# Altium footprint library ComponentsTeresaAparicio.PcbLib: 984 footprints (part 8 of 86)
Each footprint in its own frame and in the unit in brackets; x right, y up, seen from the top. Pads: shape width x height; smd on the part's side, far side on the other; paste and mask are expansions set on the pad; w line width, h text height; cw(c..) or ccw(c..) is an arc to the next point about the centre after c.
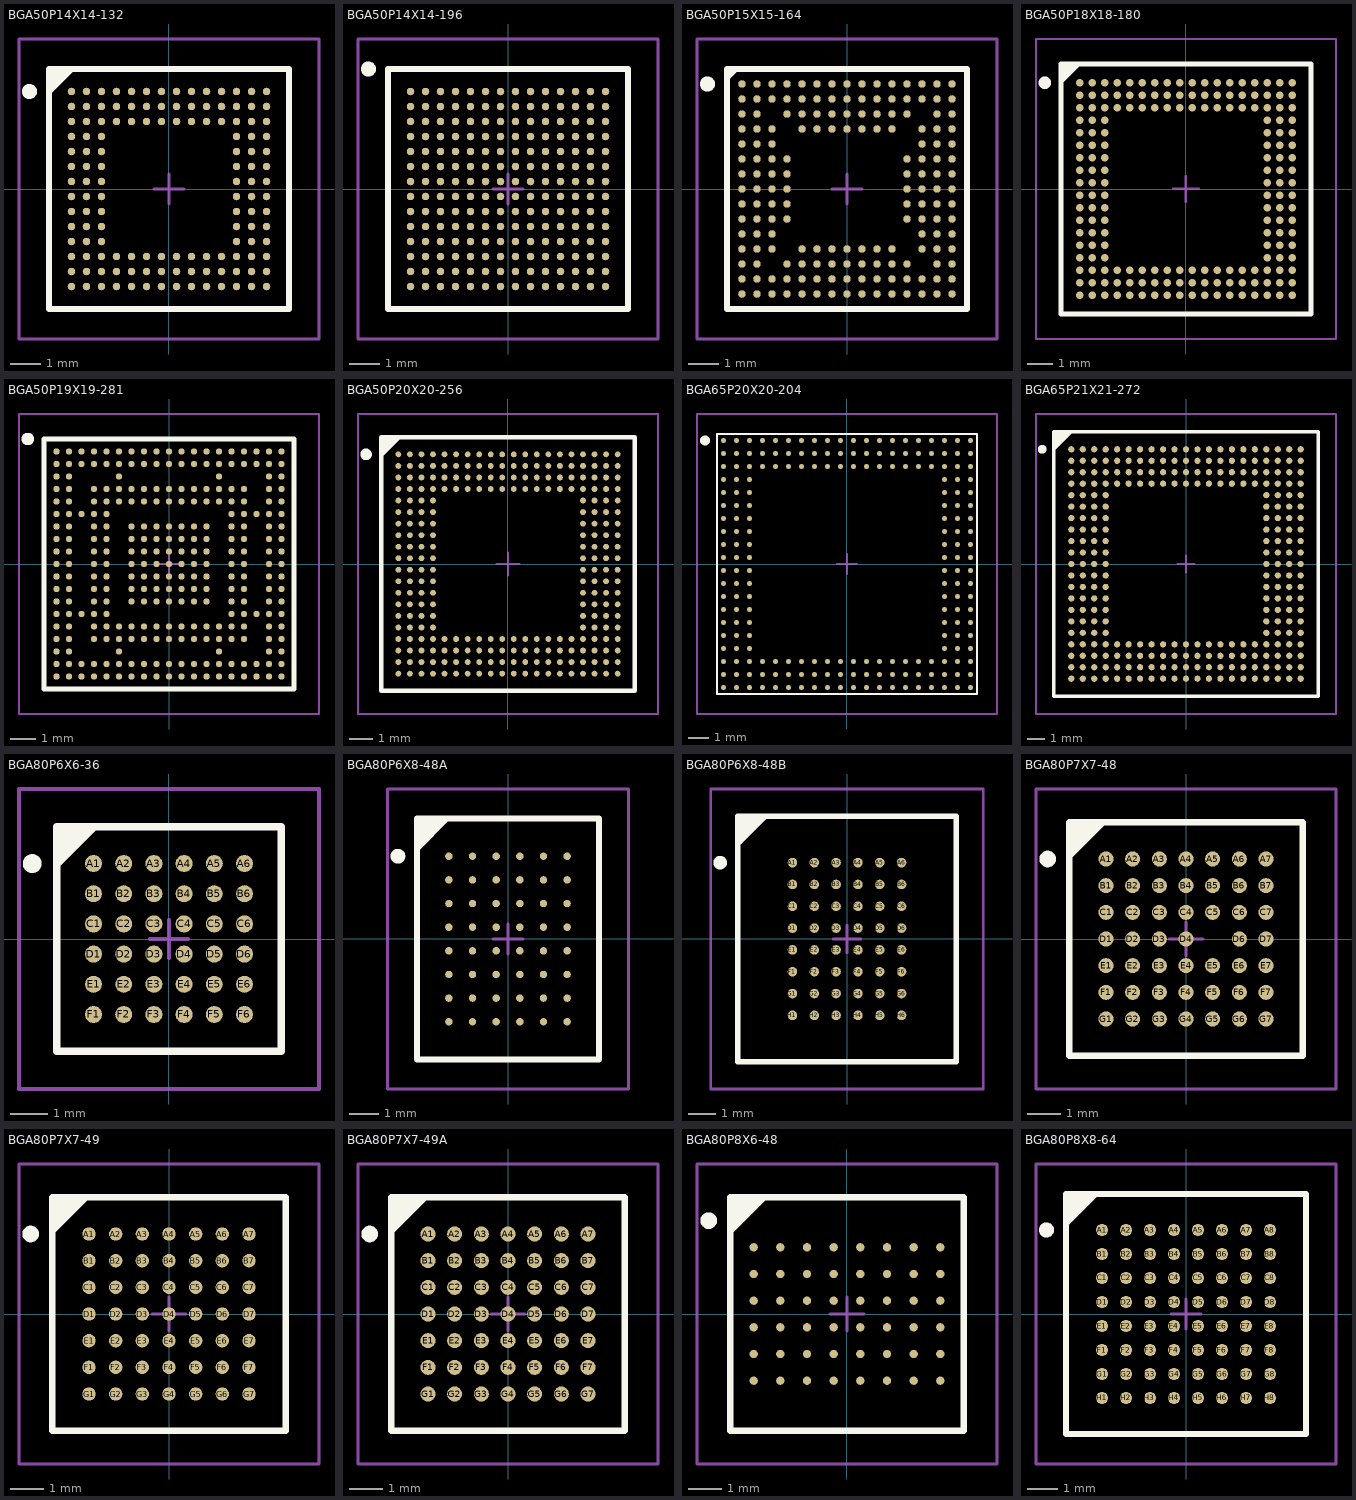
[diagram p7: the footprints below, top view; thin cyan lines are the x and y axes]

## BGA50P14X14-132 [mm] "BGA, 132-Leads, Body 8x8mm, Pitch 0.5mm"
height 1.35
pads (132):
  round 0.25 smd: A1(-3.25,3.25) A2(-2.75,3.25) A3(-2.25,3.25) A4(-1.75,3.25) A5(-1.25,3.25) A6(-0.75,3.25) A7(-0.25,3.25) A8(0.25,3.25) A9(0.75,3.25) A10(1.25,3.25) A11(1.75,3.25) A12(2.25,3.25) A13(2.75,3.25) A14(3.25,3.25) B1(-3.25,2.75) B2(-2.75,2.75) B3(-2.25,2.75) B4(-1.75,2.75) B5(-1.25,2.75) B6(-0.75,2.75) B7(-0.25,2.75) B8(0.25,2.75) B9(0.75,2.75) B10(1.25,2.75) B11(1.75,2.75) B12(2.25,2.75) B13(2.75,2.75) B14(3.25,2.75) C1(-3.25,2.25) C2(-2.75,2.25) C3(-2.25,2.25) C4(-1.75,2.25) C5(-1.25,2.25) C6(-0.75,2.25) C7(-0.25,2.25) C8(0.25,2.25) C9(0.75,2.25) C10(1.25,2.25) C11(1.75,2.25) C12(2.25,2.25) C13(2.75,2.25) C14(3.25,2.25) D1(-3.25,1.75) D2(-2.75,1.75) D3(-2.25,1.75) D12(2.25,1.75) D13(2.75,1.75) D14(3.25,1.75) E1(-3.25,1.25) E2(-2.75,1.25) E3(-2.25,1.25) E12(2.25,1.25) E13(2.75,1.25) E14(3.25,1.25) F1(-3.25,0.75) F2(-2.75,0.75) F3(-2.25,0.75) F12(2.25,0.75) F13(2.75,0.75) F14(3.25,0.75) G1(-3.25,0.25) G2(-2.75,0.25) G3(-2.25,0.25) G12(2.25,0.25) G13(2.75,0.25) G14(3.25,0.25) H1(-3.25,-0.25) H2(-2.75,-0.25) H3(-2.25,-0.25) H12(2.25,-0.25) H13(2.75,-0.25) H14(3.25,-0.25) J1(-3.25,-0.75) J2(-2.75,-0.75) J3(-2.25,-0.75) J12(2.25,-0.75) J13(2.75,-0.75) J14(3.25,-0.75) K1(-3.25,-1.25) K2(-2.75,-1.25) K3(-2.25,-1.25) K12(2.25,-1.25) K13(2.75,-1.25) K14(3.25,-1.25) L1(-3.25,-1.75) L2(-2.75,-1.75) L3(-2.25,-1.75) L12(2.25,-1.75) L13(2.75,-1.75) L14(3.25,-1.75) M1(-3.25,-2.25) M2(-2.75,-2.25) M3(-2.25,-2.25) M4(-1.75,-2.25) M5(-1.25,-2.25) M6(-0.75,-2.25) M7(-0.25,-2.25) M8(0.25,-2.25) M9(0.75,-2.25) M10(1.25,-2.25) M11(1.75,-2.25) M12(2.25,-2.25) M13(2.75,-2.25) M14(3.25,-2.25) N1(-3.25,-2.75) N2(-2.75,-2.75) N3(-2.25,-2.75) N4(-1.75,-2.75) N5(-1.25,-2.75) N6(-0.75,-2.75) N7(-0.25,-2.75) N8(0.25,-2.75) N9(0.75,-2.75) N10(1.25,-2.75) N11(1.75,-2.75) N12(2.25,-2.75) N13(2.75,-2.75) N14(3.25,-2.75) P1(-3.25,-3.25) P2(-2.75,-3.25) P3(-2.25,-3.25) P4(-1.75,-3.25) P5(-1.25,-3.25) P6(-0.75,-3.25) P7(-0.25,-3.25) P8(0.25,-3.25) P9(0.75,-3.25) P10(1.25,-3.25) P11(1.75,-3.25) P12(2.25,-3.25) P13(2.75,-3.25) P14(3.25,-3.25)
Top Overlay:
  circle w0.25: c-4.65,3.25 r0.125
  region: -3.242,4 -4,3.242 -4,4
  lines w0.2: -4,3.242 -3.242,4 ; -4,-4 -4,4 4,4 4,-4 -4,-4
Mechanical 13:
  lines w0.1: -4,-4 -4,4 4,4 4,-4 -4,-4
Mechanical 15:
  lines w0.1: -0.5,0 0.5,0 ; 0,-0.5 0,0.5 ; -5,-5 -5,5 5,5 5,-5 -5,-5
3D body: height 1.35, standoff 0, extent -4,-4 4,4

## BGA50P14X14-196 [mm] "BGA, 196-Leads, Body 8x8mm, Pitch 0.5mm"
height 1.2
pads (196):
  round 0.25 smd: A1(-3.25,3.25) A2(-2.75,3.25) A3(-2.25,3.25) A4(-1.75,3.25) A5(-1.25,3.25) A6(-0.75,3.25) A7(-0.25,3.25) A8(0.25,3.25) A9(0.75,3.25) A10(1.25,3.25) A11(1.75,3.25) A12(2.25,3.25) A13(2.75,3.25) A14(3.25,3.25) B1(-3.25,2.75) B2(-2.75,2.75) B3(-2.25,2.75) B4(-1.75,2.75) B5(-1.25,2.75) B6(-0.75,2.75) B7(-0.25,2.75) B8(0.25,2.75) B9(0.75,2.75) B10(1.25,2.75) B11(1.75,2.75) B12(2.25,2.75) B13(2.75,2.75) B14(3.25,2.75) C1(-3.25,2.25) C2(-2.75,2.25) C3(-2.25,2.25) C4(-1.75,2.25) C5(-1.25,2.25) C6(-0.75,2.25) C7(-0.25,2.25) C8(0.25,2.25) C9(0.75,2.25) C10(1.25,2.25) C11(1.75,2.25) C12(2.25,2.25) C13(2.75,2.25) C14(3.25,2.25) D1(-3.25,1.75) D2(-2.75,1.75) D3(-2.25,1.75) D4(-1.75,1.75) D5(-1.25,1.75) D6(-0.75,1.75) D7(-0.25,1.75) D8(0.25,1.75) D9(0.75,1.75) D10(1.25,1.75) D11(1.75,1.75) D12(2.25,1.75) D13(2.75,1.75) D14(3.25,1.75) E1(-3.25,1.25) E2(-2.75,1.25) E3(-2.25,1.25) E4(-1.75,1.25) E5(-1.25,1.25) E6(-0.75,1.25) E7(-0.25,1.25) E8(0.25,1.25) E9(0.75,1.25) E10(1.25,1.25) E11(1.75,1.25) E12(2.25,1.25) E13(2.75,1.25) E14(3.25,1.25) F1(-3.25,0.75) F2(-2.75,0.75) F3(-2.25,0.75) F4(-1.75,0.75) F5(-1.25,0.75) F6(-0.75,0.75) F7(-0.25,0.75) F8(0.25,0.75) F9(0.75,0.75) F10(1.25,0.75) F11(1.75,0.75) F12(2.25,0.75) F13(2.75,0.75) F14(3.25,0.75) G1(-3.25,0.25) G2(-2.75,0.25) G3(-2.25,0.25) G4(-1.75,0.25) G5(-1.25,0.25) G6(-0.75,0.25) G7(-0.25,0.25) G8(0.25,0.25) G9(0.75,0.25) G10(1.25,0.25) G11(1.75,0.25) G12(2.25,0.25) G13(2.75,0.25) G14(3.25,0.25) H1(-3.25,-0.25) H2(-2.75,-0.25) H3(-2.25,-0.25) H4(-1.75,-0.25) H5(-1.25,-0.25) H6(-0.75,-0.25) H7(-0.25,-0.25) H8(0.25,-0.25) H9(0.75,-0.25) H10(1.25,-0.25) H11(1.75,-0.25) H12(2.25,-0.25) H13(2.75,-0.25) H14(3.25,-0.25) J1(-3.25,-0.75) J2(-2.75,-0.75) J3(-2.25,-0.75) J4(-1.75,-0.75) J5(-1.25,-0.75) J6(-0.75,-0.75) J7(-0.25,-0.75) J8(0.25,-0.75) J9(0.75,-0.75) J10(1.25,-0.75) J11(1.75,-0.75) J12(2.25,-0.75) J13(2.75,-0.75) J14(3.25,-0.75) K1(-3.25,-1.25) K2(-2.75,-1.25) K3(-2.25,-1.25) K4(-1.75,-1.25) K5(-1.25,-1.25) K6(-0.75,-1.25) K7(-0.25,-1.25) K8(0.25,-1.25) K9(0.75,-1.25) K10(1.25,-1.25) K11(1.75,-1.25) K12(2.25,-1.25) K13(2.75,-1.25) K14(3.25,-1.25) L1(-3.25,-1.75) L2(-2.75,-1.75) L3(-2.25,-1.75) L4(-1.75,-1.75) L5(-1.25,-1.75) L6(-0.75,-1.75) L7(-0.25,-1.75) L8(0.25,-1.75) L9(0.75,-1.75) L10(1.25,-1.75) L11(1.75,-1.75) L12(2.25,-1.75) L13(2.75,-1.75) L14(3.25,-1.75) M1(-3.25,-2.25) M2(-2.75,-2.25) M3(-2.25,-2.25) M4(-1.75,-2.25) M5(-1.25,-2.25) M6(-0.75,-2.25) M7(-0.25,-2.25) M8(0.25,-2.25) M9(0.75,-2.25) M10(1.25,-2.25) M11(1.75,-2.25) M12(2.25,-2.25) M13(2.75,-2.25) M14(3.25,-2.25) N1(-3.25,-2.75) N2(-2.75,-2.75) N3(-2.25,-2.75) N4(-1.75,-2.75) N5(-1.25,-2.75) N6(-0.75,-2.75) N7(-0.25,-2.75) N8(0.25,-2.75) N9(0.75,-2.75) N10(1.25,-2.75) N11(1.75,-2.75) N12(2.25,-2.75) N13(2.75,-2.75) N14(3.25,-2.75) P1(-3.25,-3.25) P2(-2.75,-3.25) P3(-2.25,-3.25) P4(-1.75,-3.25) P5(-1.25,-3.25) P6(-0.75,-3.25) P7(-0.25,-3.25) P8(0.25,-3.25) P9(0.75,-3.25) P10(1.25,-3.25) P11(1.75,-3.25) P12(2.25,-3.25) P13(2.75,-3.25) P14(3.25,-3.25)
Top Overlay:
  circle w0.25: c-4.65,4 r0.125
  lines w0.2: -4,-4 4,-4 4,4 -4,4 -4,-4
Mechanical 13:
  lines w0.1: -4,-4 4,-4 4,4 -4,4 -4,-4
Mechanical 15:
  lines w0.1: -0.5,0 0.5,0 ; 0,-0.5 0,0.5 ; -5,-5 5,-5 5,5 -5,5 -5,-5
3D body: height 1.2, standoff 0.15, extent -4,-4 4,4

## BGA50P15X15-164 [mm] "BGA, 164-Leads, Body 8x8mm, Pitch 0.50mm"
height 1.2
pads (164):
  round 0.25 smd: A1(-3.5,3.5) A2(-3,3.5) A3(-2.5,3.5) A4(-2,3.5) A5(-1.5,3.5) A6(-1,3.5) A7(-0.5,3.5) A8(0,3.5) A9(0.5,3.5) A10(1,3.5) A11(1.5,3.5) A12(2,3.5) A13(2.5,3.5) A14(3,3.5) A15(3.5,3.5) B1(-3.5,3) B2(-3,3) B3(-2.5,3) B4(-2,3) B5(-1.5,3) B6(-1,3) B7(-0.5,3) B8(0,3) B9(0.5,3) B10(1,3) B11(1.5,3) B12(2,3) B13(2.5,3) B14(3,3) B15(3.5,3) C1(-3.5,2.5) C2(-3,2.5) C4(-2,2.5) C5(-1.5,2.5) C6(-1,2.5) C7(-0.5,2.5) C8(0,2.5) C9(0.5,2.5) C10(1,2.5) C11(1.5,2.5) C12(2,2.5) C14(3,2.5) C15(3.5,2.5) D1(-3.5,2) D2(-3,2) D3(-2.5,2) D5(-1.5,2) D6(-1,2) D7(-0.5,2) D8(0,2) D9(0.5,2) D10(1,2) D11(1.5,2) D13(2.5,2) D14(3,2) D15(3.5,2) E1(-3.5,1.5) E2(-3,1.5) E3(-2.5,1.5) E13(2.5,1.5) E14(3,1.5) E15(3.5,1.5) F1(-3.5,1) F2(-3,1) F3(-2.5,1) F4(-2,1) F12(2,1) F13(2.5,1) F14(3,1) F15(3.5,1) G1(-3.5,0.5) G2(-3,0.5) G3(-2.5,0.5) G4(-2,0.5) G12(2,0.5) G13(2.5,0.5) G14(3,0.5) G15(3.5,0.5) H1(-3.5,0) H2(-3,0) H3(-2.5,0) H4(-2,0) H12(2,0) H13(2.5,0) H14(3,0) H15(3.5,0) J1(-3.5,-0.5) J2(-3,-0.5) J3(-2.5,-0.5) J4(-2,-0.5) J12(2,-0.5) J13(2.5,-0.5) J14(3,-0.5) J15(3.5,-0.5) K1(-3.5,-1) K2(-3,-1) K3(-2.5,-1) K4(-2,-1) K12(2,-1) K13(2.5,-1) K14(3,-1) K15(3.5,-1) L1(-3.5,-1.5) L2(-3,-1.5) L3(-2.5,-1.5) L13(2.5,-1.5) L14(3,-1.5) L15(3.5,-1.5) M1(-3.5,-2) M2(-3,-2) M3(-2.5,-2) M5(-1.5,-2) M6(-1,-2) M7(-0.5,-2) M8(0,-2) M9(0.5,-2) M10(1,-2) M11(1.5,-2) M13(2.5,-2) M14(3,-2) M15(3.5,-2) N1(-3.5,-2.5) N2(-3,-2.5) N4(-2,-2.5) N5(-1.5,-2.5) N6(-1,-2.5) N7(-0.5,-2.5) N8(0,-2.5) N9(0.5,-2.5) N10(1,-2.5) N11(1.5,-2.5) N12(2,-2.5) N14(3,-2.5) N15(3.5,-2.5) P1(-3.5,-3) P2(-3,-3) P3(-2.5,-3) P4(-2,-3) P5(-1.5,-3) P6(-1,-3) P7(-0.5,-3) P8(0,-3) P9(0.5,-3) P10(1,-3) P11(1.5,-3) P12(2,-3) P13(2.5,-3) P14(3,-3) P15(3.5,-3) R1(-3.5,-3.5) R2(-3,-3.5) R3(-2.5,-3.5) R4(-2,-3.5) R5(-1.5,-3.5) R6(-1,-3.5) R7(-0.5,-3.5) R8(0,-3.5) R9(0.5,-3.5) R10(1,-3.5) R11(1.5,-3.5) R12(2,-3.5) R13(2.5,-3.5) R14(3,-3.5) R15(3.5,-3.5)
Top Overlay:
  circle w0.25: c-4.65,3.5 r0.125
  region: -3.707,4 -4,3.707 -4,4
  lines w0.2: -4,3.707 -3.707,4 ; -4,-4 -4,4 4,4 4,-4 -4,-4
Mechanical 13:
  lines w0.1: -4,-4 -4,4 4,4 4,-4 -4,-4
Mechanical 15:
  lines w0.1: -0.5,0 0.5,0 ; 0,-0.5 0,0.5 ; -5,-5 -5,5 5,5 5,-5 -5,-5
3D body: height 1.2, standoff 0.15, extent -4,-4 4,4

## BGA50P18X18-180 [mm] "BGA, 180-Leads, Body 10x10mm, Pitch 0.5mm"
height 1.11
pads (180):
  round 0.3 smd: A1(-4.25,4.25) A2(-3.75,4.25) A3(-3.25,4.25) A4(-2.75,4.25) A5(-2.25,4.25) A6(-1.75,4.25) A7(-1.25,4.25) A8(-0.75,4.25) A9(-0.25,4.25) A10(0.25,4.25) A11(0.75,4.25) A12(1.25,4.25) A13(1.75,4.25) A14(2.25,4.25) A15(2.75,4.25) A16(3.25,4.25) A17(3.75,4.25) A18(4.25,4.25) B1(-4.25,3.75) B2(-3.75,3.75) B3(-3.25,3.75) B4(-2.75,3.75) B5(-2.25,3.75) B6(-1.75,3.75) B7(-1.25,3.75) B8(-0.75,3.75) B9(-0.25,3.75) B10(0.25,3.75) B11(0.75,3.75) B12(1.25,3.75) B13(1.75,3.75) B14(2.25,3.75) B15(2.75,3.75) B16(3.25,3.75) B17(3.75,3.75) B18(4.25,3.75) C1(-4.25,3.25) C2(-3.75,3.25) C3(-3.25,3.25) C4(-2.75,3.25) C5(-2.25,3.25) C6(-1.75,3.25) C7(-1.25,3.25) C8(-0.75,3.25) C9(-0.25,3.25) C10(0.25,3.25) C11(0.75,3.25) C12(1.25,3.25) C13(1.75,3.25) C14(2.25,3.25) C15(2.75,3.25) C16(3.25,3.25) C17(3.75,3.25) C18(4.25,3.25) D1(-4.25,2.75) D2(-3.75,2.75) D3(-3.25,2.75) D16(3.25,2.75) D17(3.75,2.75) D18(4.25,2.75) E1(-4.25,2.25) E2(-3.75,2.25) E3(-3.25,2.25) E16(3.25,2.25) E17(3.75,2.25) E18(4.25,2.25) F1(-4.25,1.75) F2(-3.75,1.75) F3(-3.25,1.75) F16(3.25,1.75) F17(3.75,1.75) F18(4.25,1.75) G1(-4.25,1.25) G2(-3.75,1.25) G3(-3.25,1.25) G16(3.25,1.25) G17(3.75,1.25) G18(4.25,1.25) H1(-4.25,0.75) H2(-3.75,0.75) H3(-3.25,0.75) H16(3.25,0.75) H17(3.75,0.75) H18(4.25,0.75) J1(-4.25,0.25) J2(-3.75,0.25) J3(-3.25,0.25) J16(3.25,0.25) J17(3.75,0.25) J18(4.25,0.25) K1(-4.25,-0.25) K2(-3.75,-0.25) K3(-3.25,-0.25) K16(3.25,-0.25) K17(3.75,-0.25) K18(4.25,-0.25) L1(-4.25,-0.75) L2(-3.75,-0.75) L3(-3.25,-0.75) L16(3.25,-0.75) L17(3.75,-0.75) L18(4.25,-0.75) M1(-4.25,-1.25) M2(-3.75,-1.25) M3(-3.25,-1.25) M16(3.25,-1.25) M17(3.75,-1.25) M18(4.25,-1.25) N1(-4.25,-1.75) N2(-3.75,-1.75) N3(-3.25,-1.75) N16(3.25,-1.75) N17(3.75,-1.75) N18(4.25,-1.75) P1(-4.25,-2.25) P2(-3.75,-2.25) P3(-3.25,-2.25) P16(3.25,-2.25) P17(3.75,-2.25) P18(4.25,-2.25) R1(-4.25,-2.75) R2(-3.75,-2.75) R3(-3.25,-2.75) R16(3.25,-2.75) R17(3.75,-2.75) R18(4.25,-2.75) T1(-4.25,-3.25) T2(-3.75,-3.25) T3(-3.25,-3.25) T4(-2.75,-3.25) T5(-2.25,-3.25) T6(-1.75,-3.25) T7(-1.25,-3.25) T8(-0.75,-3.25) T9(-0.25,-3.25) T10(0.25,-3.25) T11(0.75,-3.25) T12(1.25,-3.25) T13(1.75,-3.25) T14(2.25,-3.25) T15(2.75,-3.25) T16(3.25,-3.25) T17(3.75,-3.25) T18(4.25,-3.25) U1(-4.25,-3.75) U2(-3.75,-3.75) U3(-3.25,-3.75) U4(-2.75,-3.75) U5(-2.25,-3.75) U6(-1.75,-3.75) U7(-1.25,-3.75) U8(-0.75,-3.75) U9(-0.25,-3.75) U10(0.25,-3.75) U11(0.75,-3.75) U12(1.25,-3.75) U13(1.75,-3.75) U14(2.25,-3.75) U15(2.75,-3.75) U16(3.25,-3.75) U17(3.75,-3.75) U18(4.25,-3.75) V1(-4.25,-4.25) V2(-3.75,-4.25) V3(-3.25,-4.25) V4(-2.75,-4.25) V5(-2.25,-4.25) V6(-1.75,-4.25) V7(-1.25,-4.25) V8(-0.75,-4.25) V9(-0.25,-4.25) V10(0.25,-4.25) V11(0.75,-4.25) V12(1.25,-4.25) V13(1.75,-4.25) V14(2.25,-4.25) V15(2.75,-4.25) V16(3.25,-4.25) V17(3.75,-4.25) V18(4.25,-4.25)
Top Overlay:
  circle w0.25: c-5.65,4.25 r0.125
  region: -4.306,5 -5,4.306 -5,5
  lines w0.2: -5,4.306 -4.306,5 ; -5,-5 -5,5 5,5 5,-5 -5,-5
Mechanical 13:
  lines w0.1: -5,-5 -5,5 5,5 5,-5 -5,-5
Mechanical 15:
  lines w0.1: -0.5,0 0.5,0 ; 0,-0.5 0,0.5 ; -6,-6 -6,6 6,6 6,-6 -6,-6
3D body: height 1.11, standoff 0.19, extent -5,-5 5,5

## BGA50P19X19-281 [mm] "BGA, 281-Leads, Body 10x10mm, Pitch 0.5mm"
height 1.05
pads (281):
  round 0.25 smd: A1(-4.5,4.5) A2(-4,4.5) A3(-3.5,4.5) A4(-3,4.5) A5(-2.5,4.5) A6(-2,4.5) A7(-1.5,4.5) A8(-1,4.5) A9(-0.5,4.5) A10(0,4.5) A11(0.5,4.5) A12(1,4.5) A13(1.5,4.5) A14(2,4.5) A15(2.5,4.5) A16(3,4.5) A17(3.5,4.5) A18(4,4.5) A19(4.5,4.5) B1(-4.5,4) B2(-4,4) B3(-3.5,4) B4(-3,4) B5(-2.5,4) B6(-2,4) B7(-1.5,4) B8(-1,4) B9(-0.5,4) B10(0,4) B11(0.5,4) B12(1,4) B13(1.5,4) B14(2,4) B15(2.5,4) B16(3,4) B17(3.5,4) B18(4,4) B19(4.5,4) C1(-4.5,3.5) C2(-4,3.5) C6(-2,3.5) C14(2,3.5) C18(4,3.5) C19(4.5,3.5) D1(-4.5,3) D2(-4,3) D4(-3,3) D5(-2.5,3) D6(-2,3) D7(-1.5,3) D8(-1,3) D9(-0.5,3) D10(0,3) D11(0.5,3) D12(1,3) D13(1.5,3) D14(2,3) D15(2.5,3) D16(3,3) D18(4,3) D19(4.5,3) E1(-4.5,2.5) E2(-4,2.5) E4(-3,2.5) E5(-2.5,2.5) E6(-2,2.5) E7(-1.5,2.5) E8(-1,2.5) E9(-0.5,2.5) E10(0,2.5) E11(0.5,2.5) E12(1,2.5) E13(1.5,2.5) E14(2,2.5) E15(2.5,2.5) E16(3,2.5) E18(4,2.5) E19(4.5,2.5) F1(-4.5,2) F2(-4,2) F3(-3.5,2) F4(-3,2) F5(-2.5,2) F15(2.5,2) F16(3,2) F17(3.5,2) F18(4,2) F19(4.5,2) G1(-4.5,1.5) G2(-4,1.5) G4(-3,1.5) G5(-2.5,1.5) G7(-1.5,1.5) G8(-1,1.5) G9(-0.5,1.5) G10(0,1.5) G11(0.5,1.5) G12(1,1.5) G13(1.5,1.5) G15(2.5,1.5) G16(3,1.5) G18(4,1.5) G19(4.5,1.5) H1(-4.5,1) H2(-4,1) H4(-3,1) H5(-2.5,1) H7(-1.5,1) H8(-1,1) H9(-0.5,1) H10(0,1) H11(0.5,1) H12(1,1) H13(1.5,1) H15(2.5,1) H16(3,1) H18(4,1) H19(4.5,1) J1(-4.5,0.5) J2(-4,0.5) J4(-3,0.5) J5(-2.5,0.5) J7(-1.5,0.5) J8(-1,0.5) J9(-0.5,0.5) J10(0,0.5) J11(0.5,0.5) J12(1,0.5) J13(1.5,0.5) J15(2.5,0.5) J16(3,0.5) J18(4,0.5) J19(4.5,0.5) K1(-4.5,0) K2(-4,0) K4(-3,0) K5(-2.5,0) K7(-1.5,0) K8(-1,0) K9(-0.5,0) K10(0,0) K11(0.5,0) K12(1,0) K13(1.5,0) K15(2.5,0) K16(3,0) K18(4,0) K19(4.5,0) L1(-4.5,-0.5) L2(-4,-0.5) L4(-3,-0.5) L5(-2.5,-0.5) L7(-1.5,-0.5) L8(-1,-0.5) L9(-0.5,-0.5) L10(0,-0.5) L11(0.5,-0.5) L12(1,-0.5) L13(1.5,-0.5) L15(2.5,-0.5) L16(3,-0.5) L18(4,-0.5) L19(4.5,-0.5) M1(-4.5,-1) M2(-4,-1) M4(-3,-1) M5(-2.5,-1) M7(-1.5,-1) M8(-1,-1) M9(-0.5,-1) M10(0,-1) M11(0.5,-1) M12(1,-1) M13(1.5,-1) M15(2.5,-1) M16(3,-1) M18(4,-1) M19(4.5,-1) N1(-4.5,-1.5) N2(-4,-1.5) N4(-3,-1.5) N5(-2.5,-1.5) N7(-1.5,-1.5) N8(-1,-1.5) N9(-0.5,-1.5) N10(0,-1.5) N11(0.5,-1.5) N12(1,-1.5) N13(1.5,-1.5) N15(2.5,-1.5) N16(3,-1.5) N18(4,-1.5) N19(4.5,-1.5) P1(-4.5,-2) P2(-4,-2) P3(-3.5,-2) P4(-3,-2) P5(-2.5,-2) P15(2.5,-2) P16(3,-2) P17(3.5,-2) P18(4,-2) P19(4.5,-2) R1(-4.5,-2.5) R2(-4,-2.5) R4(-3,-2.5) R5(-2.5,-2.5) R6(-2,-2.5) R7(-1.5,-2.5) R8(-1,-2.5) R9(-0.5,-2.5) R10(0,-2.5) R11(0.5,-2.5) R12(1,-2.5) R13(1.5,-2.5) R14(2,-2.5) R15(2.5,-2.5) R16(3,-2.5) R18(4,-2.5) R19(4.5,-2.5) T1(-4.5,-3) T2(-4,-3) T4(-3,-3) T5(-2.5,-3) T6(-2,-3) T7(-1.5,-3) T8(-1,-3) T9(-0.5,-3) T10(0,-3) T11(0.5,-3) T12(1,-3) T13(1.5,-3) T14(2,-3) T15(2.5,-3) T16(3,-3) T18(4,-3) T19(4.5,-3) U1(-4.5,-3.5) U2(-4,-3.5) U6(-2,-3.5) U14(2,-3.5) U18(4,-3.5) U19(4.5,-3.5) V1(-4.5,-4) V2(-4,-4) V3(-3.5,-4) V4(-3,-4) V5(-2.5,-4) V6(-2,-4) V7(-1.5,-4) V8(-1,-4) V9(-0.5,-4) V10(0,-4) V11(0.5,-4) V12(1,-4) V13(1.5,-4) V14(2,-4) V15(2.5,-4) V16(3,-4) V17(3.5,-4) V18(4,-4) V19(4.5,-4) W1(-4.5,-4.5) W2(-4,-4.5) W3(-3.5,-4.5) W4(-3,-4.5) W5(-2.5,-4.5) W6(-2,-4.5) W7(-1.5,-4.5) W8(-1,-4.5) W9(-0.5,-4.5) W10(0,-4.5) W11(0.5,-4.5) W12(1,-4.5) W13(1.5,-4.5) W14(2,-4.5) W15(2.5,-4.5) W16(3,-4.5) W17(3.5,-4.5) W18(4,-4.5) W19(4.5,-4.5)
Top Overlay:
  circle w0.25: c-5.65,5 r0.125
  lines w0.2: -5,-5 5,-5 5,5 -5,5 -5,-5
Mechanical 13:
  lines w0.1: -5,-5 5,-5 5,5 -5,5 -5,-5
Mechanical 15:
  lines w0.1: -0.5,0 0.5,0 ; 0,-0.5 0,0.5 ; -6,-6 6,-6 6,6 -6,6 -6,-6
3D body: height 1.05, standoff 0.18, extent -5,-5 5,5

## BGA50P20X20-256 [mm] "BGA, 256-Leads, Body 11x11mm, Pitch 0.5mm"
height 1.2
pads (256):
  round 0.25 smd: A1(-4.75,4.75) A2(-4.25,4.75) A3(-3.75,4.75) A4(-3.25,4.75) A5(-2.75,4.75) A6(-2.25,4.75) A7(-1.75,4.75) A8(-1.25,4.75) A9(-0.75,4.75) A10(-0.25,4.75) A11(0.25,4.75) A12(0.75,4.75) A13(1.25,4.75) A14(1.75,4.75) A15(2.25,4.75) A16(2.75,4.75) A17(3.25,4.75) A18(3.75,4.75) A19(4.25,4.75) A20(4.75,4.75) B1(-4.75,4.25) B2(-4.25,4.25) B3(-3.75,4.25) B4(-3.25,4.25) B5(-2.75,4.25) B6(-2.25,4.25) B7(-1.75,4.25) B8(-1.25,4.25) B9(-0.75,4.25) B10(-0.25,4.25) B11(0.25,4.25) B12(0.75,4.25) B13(1.25,4.25) B14(1.75,4.25) B15(2.25,4.25) B16(2.75,4.25) B17(3.25,4.25) B18(3.75,4.25) B19(4.25,4.25) B20(4.75,4.25) C1(-4.75,3.75) C2(-4.25,3.75) C3(-3.75,3.75) C4(-3.25,3.75) C5(-2.75,3.75) C6(-2.25,3.75) C7(-1.75,3.75) C8(-1.25,3.75) C9(-0.75,3.75) C10(-0.25,3.75) C11(0.25,3.75) C12(0.75,3.75) C13(1.25,3.75) C14(1.75,3.75) C15(2.25,3.75) C16(2.75,3.75) C17(3.25,3.75) C18(3.75,3.75) C19(4.25,3.75) C20(4.75,3.75) D1(-4.75,3.25) D2(-4.25,3.25) D3(-3.75,3.25) D4(-3.25,3.25) D5(-2.75,3.25) D6(-2.25,3.25) D7(-1.75,3.25) D8(-1.25,3.25) D9(-0.75,3.25) D10(-0.25,3.25) D11(0.25,3.25) D12(0.75,3.25) D13(1.25,3.25) D14(1.75,3.25) D15(2.25,3.25) D16(2.75,3.25) D17(3.25,3.25) D18(3.75,3.25) D19(4.25,3.25) D20(4.75,3.25) E1(-4.75,2.75) E2(-4.25,2.75) E3(-3.75,2.75) E4(-3.25,2.75) E17(3.25,2.75) E18(3.75,2.75) E19(4.25,2.75) E20(4.75,2.75) F1(-4.75,2.25) F2(-4.25,2.25) F3(-3.75,2.25) F4(-3.25,2.25) F17(3.25,2.25) F18(3.75,2.25) F19(4.25,2.25) F20(4.75,2.25) G1(-4.75,1.75) G2(-4.25,1.75) G3(-3.75,1.75) G4(-3.25,1.75) G17(3.25,1.75) G18(3.75,1.75) G19(4.25,1.75) G20(4.75,1.75) H1(-4.75,1.25) H2(-4.25,1.25) H3(-3.75,1.25) H4(-3.25,1.25) H17(3.25,1.25) H18(3.75,1.25) H19(4.25,1.25) H20(4.75,1.25) J1(-4.75,0.75) J2(-4.25,0.75) J3(-3.75,0.75) J4(-3.25,0.75) J17(3.25,0.75) J18(3.75,0.75) J19(4.25,0.75) J20(4.75,0.75) K1(-4.75,0.25) K2(-4.25,0.25) K3(-3.75,0.25) K4(-3.25,0.25) K17(3.25,0.25) K18(3.75,0.25) K19(4.25,0.25) K20(4.75,0.25) L1(-4.75,-0.25) L2(-4.25,-0.25) L3(-3.75,-0.25) L4(-3.25,-0.25) L17(3.25,-0.25) L18(3.75,-0.25) L19(4.25,-0.25) L20(4.75,-0.25) M1(-4.75,-0.75) M2(-4.25,-0.75) M3(-3.75,-0.75) M4(-3.25,-0.75) M17(3.25,-0.75) M18(3.75,-0.75) M19(4.25,-0.75) M20(4.75,-0.75) N1(-4.75,-1.25) N2(-4.25,-1.25) N3(-3.75,-1.25) N4(-3.25,-1.25) N17(3.25,-1.25) N18(3.75,-1.25) N19(4.25,-1.25) N20(4.75,-1.25) P1(-4.75,-1.75) P2(-4.25,-1.75) P3(-3.75,-1.75) P4(-3.25,-1.75) P17(3.25,-1.75) P18(3.75,-1.75) P19(4.25,-1.75) P20(4.75,-1.75) R1(-4.75,-2.25) R2(-4.25,-2.25) R3(-3.75,-2.25) R4(-3.25,-2.25) R17(3.25,-2.25) R18(3.75,-2.25) R19(4.25,-2.25) R20(4.75,-2.25) T1(-4.75,-2.75) T2(-4.25,-2.75) T3(-3.75,-2.75) T4(-3.25,-2.75) T17(3.25,-2.75) T18(3.75,-2.75) T19(4.25,-2.75) T20(4.75,-2.75) U1(-4.75,-3.25) U2(-4.25,-3.25) U3(-3.75,-3.25) U4(-3.25,-3.25) U5(-2.75,-3.25) U6(-2.25,-3.25) U7(-1.75,-3.25) U8(-1.25,-3.25) U9(-0.75,-3.25) U10(-0.25,-3.25) U11(0.25,-3.25) U12(0.75,-3.25) U13(1.25,-3.25) U14(1.75,-3.25) U15(2.25,-3.25) U16(2.75,-3.25) U17(3.25,-3.25) U18(3.75,-3.25) U19(4.25,-3.25) U20(4.75,-3.25) V1(-4.75,-3.75) V2(-4.25,-3.75) V3(-3.75,-3.75) V4(-3.25,-3.75) V5(-2.75,-3.75) V6(-2.25,-3.75) V7(-1.75,-3.75) V8(-1.25,-3.75) V9(-0.75,-3.75) V10(-0.25,-3.75) V11(0.25,-3.75) V12(0.75,-3.75) V13(1.25,-3.75) V14(1.75,-3.75) V15(2.25,-3.75) V16(2.75,-3.75) V17(3.25,-3.75) V18(3.75,-3.75) V19(4.25,-3.75) V20(4.75,-3.75) W1(-4.75,-4.25) W2(-4.25,-4.25) W3(-3.75,-4.25) W4(-3.25,-4.25) W5(-2.75,-4.25) W6(-2.25,-4.25) W7(-1.75,-4.25) W8(-1.25,-4.25) W9(-0.75,-4.25) W10(-0.25,-4.25) W11(0.25,-4.25) W12(0.75,-4.25) W13(1.25,-4.25) W14(1.75,-4.25) W15(2.25,-4.25) W16(2.75,-4.25) W17(3.25,-4.25) W18(3.75,-4.25) W19(4.25,-4.25) W20(4.75,-4.25) Y1(-4.75,-4.75) Y2(-4.25,-4.75) Y3(-3.75,-4.75) Y4(-3.25,-4.75) Y5(-2.75,-4.75) Y6(-2.25,-4.75) Y7(-1.75,-4.75) Y8(-1.25,-4.75) Y9(-0.75,-4.75) Y10(-0.25,-4.75) Y11(0.25,-4.75) Y12(0.75,-4.75) Y13(1.25,-4.75) Y14(1.75,-4.75) Y15(2.25,-4.75) Y16(2.75,-4.75) Y17(3.25,-4.75) Y18(3.75,-4.75) Y19(4.25,-4.75) Y20(4.75,-4.75)
Top Overlay:
  circle w0.25: c-6.15,4.75 r0.125
  region: -4.742,5.5 -5.5,4.742 -5.5,5.5
  lines w0.2: -5.5,4.742 -4.742,5.5 ; -5.5,-5.5 5.5,-5.5 5.5,5.5 -5.5,5.5 -5.5,-5.5
Mechanical 13:
  lines w0.1: -5.5,-5.5 5.5,-5.5 5.5,5.5 -5.5,5.5 -5.5,-5.5
Mechanical 15:
  lines w0.1: -0.5,0 0.5,0 ; 0,-0.5 0,0.5 ; -6.5,-6.5 6.5,-6.5 6.5,6.5 -6.5,6.5 -6.5,-6.5
3D body: height 0, standoff 0, extent -5.499,-5.499 5.499,5.499

## BGA65P20X20-204 [mm] "BGA, 204-Leads, Body 13x13mm, Pitch 0.65mm"
height 1.2
pads (204):
  round 0.25 smd: A1(-6.175,6.175) A2(-5.525,6.175) A3(-4.875,6.175) A4(-4.225,6.175) A5(-3.575,6.175) A6(-2.925,6.175) A7(-2.275,6.175) A8(-1.625,6.175) A9(-0.975,6.175) A10(-0.325,6.175) A11(0.325,6.175) A12(0.975,6.175) A13(1.625,6.175) A14(2.275,6.175) A15(2.925,6.175) A16(3.575,6.175) A17(4.225,6.175) A18(4.875,6.175) A19(5.525,6.175) A20(6.175,6.175) B1(-6.175,5.525) B2(-5.525,5.525) B3(-4.875,5.525) B4(-4.225,5.525) B5(-3.575,5.525) B6(-2.925,5.525) B7(-2.275,5.525) B8(-1.625,5.525) B9(-0.975,5.525) B10(-0.325,5.525) B11(0.325,5.525) B12(0.975,5.525) B13(1.625,5.525) B14(2.275,5.525) B15(2.925,5.525) B16(3.575,5.525) B17(4.225,5.525) B18(4.875,5.525) B19(5.525,5.525) B20(6.175,5.525) C1(-6.175,4.875) C2(-5.525,4.875) C3(-4.875,4.875) C4(-4.225,4.875) C5(-3.575,4.875) C6(-2.925,4.875) C7(-2.275,4.875) C8(-1.625,4.875) C9(-0.975,4.875) C10(-0.325,4.875) C11(0.325,4.875) C12(0.975,4.875) C13(1.625,4.875) C14(2.275,4.875) C15(2.925,4.875) C16(3.575,4.875) C17(4.225,4.875) C18(4.875,4.875) C19(5.525,4.875) C20(6.175,4.875) D1(-6.175,4.225) D2(-5.525,4.225) D3(-4.875,4.225) D18(4.875,4.225) D19(5.525,4.225) D20(6.175,4.225) E1(-6.175,3.575) E2(-5.525,3.575) E3(-4.875,3.575) E18(4.875,3.575) E19(5.525,3.575) E20(6.175,3.575) F1(-6.175,2.925) F2(-5.525,2.925) F3(-4.875,2.925) F18(4.875,2.925) F19(5.525,2.925) F20(6.175,2.925) G1(-6.175,2.275) G2(-5.525,2.275) G3(-4.875,2.275) G18(4.875,2.275) G19(5.525,2.275) G20(6.175,2.275) H1(-6.175,1.625) H2(-5.525,1.625) H3(-4.875,1.625) H18(4.875,1.625) H19(5.525,1.625) H20(6.175,1.625) J1(-6.175,0.975) J2(-5.525,0.975) J3(-4.875,0.975) J18(4.875,0.975) J19(5.525,0.975) J20(6.175,0.975) K1(-6.175,0.325) K2(-5.525,0.325) K3(-4.875,0.325) K18(4.875,0.325) K19(5.525,0.325) K20(6.175,0.325) L1(-6.175,-0.325) L2(-5.525,-0.325) L3(-4.875,-0.325) L18(4.875,-0.325) L19(5.525,-0.325) L20(6.175,-0.325) M1(-6.175,-0.975) M2(-5.525,-0.975) M3(-4.875,-0.975) M18(4.875,-0.975) M19(5.525,-0.975) M20(6.175,-0.975) N1(-6.175,-1.625) N2(-5.525,-1.625) N3(-4.875,-1.625) N18(4.875,-1.625) N19(5.525,-1.625) N20(6.175,-1.625) P1(-6.175,-2.275) P2(-5.525,-2.275) P3(-4.875,-2.275) P18(4.875,-2.275) P19(5.525,-2.275) P20(6.175,-2.275) R1(-6.175,-2.925) R2(-5.525,-2.925) R3(-4.875,-2.925) R18(4.875,-2.925) R19(5.525,-2.925) R20(6.175,-2.925) T1(-6.175,-3.575) T2(-5.525,-3.575) T3(-4.875,-3.575) T18(4.875,-3.575) T19(5.525,-3.575) T20(6.175,-3.575) U1(-6.175,-4.225) U2(-5.525,-4.225) U3(-4.875,-4.225) U18(4.875,-4.225) U19(5.525,-4.225) U20(6.175,-4.225) V1(-6.175,-4.875) V2(-5.525,-4.875) V3(-4.875,-4.875) V4(-4.225,-4.875) V5(-3.575,-4.875) V6(-2.925,-4.875) V7(-2.275,-4.875) V8(-1.625,-4.875) V9(-0.975,-4.875) V10(-0.325,-4.875) V11(0.325,-4.875) V12(0.975,-4.875) V13(1.625,-4.875) V14(2.275,-4.875) V15(2.925,-4.875) V16(3.575,-4.875) V17(4.225,-4.875) V18(4.875,-4.875) V19(5.525,-4.875) V20(6.175,-4.875) W1(-6.175,-5.525) W2(-5.525,-5.525) W3(-4.875,-5.525) W4(-4.225,-5.525) W5(-3.575,-5.525) W6(-2.925,-5.525) W7(-2.275,-5.525) W8(-1.625,-5.525) W9(-0.975,-5.525) W10(-0.325,-5.525) W11(0.325,-5.525) W12(0.975,-5.525) W13(1.625,-5.525) W14(2.275,-5.525) W15(2.925,-5.525) W16(3.575,-5.525) W17(4.225,-5.525) W18(4.875,-5.525) W19(5.525,-5.525) W20(6.175,-5.525) Y1(-6.175,-6.175) Y2(-5.525,-6.175) Y3(-4.875,-6.175) Y4(-4.225,-6.175) Y5(-3.575,-6.175) Y6(-2.925,-6.175) Y7(-2.275,-6.175) Y8(-1.625,-6.175) Y9(-0.975,-6.175) Y10(-0.325,-6.175) Y11(0.325,-6.175) Y12(0.975,-6.175) Y13(1.625,-6.175) Y14(2.275,-6.175) Y15(2.925,-6.175) Y16(3.575,-6.175) Y17(4.225,-6.175) Y18(4.875,-6.175) Y19(5.525,-6.175) Y20(6.175,-6.175)
Top Overlay:
  circle w0.25: c-7.1,6.175 r0.125
  lines w0.1: -6.5,-6.5 6.5,-6.5 6.5,6.5 -6.5,6.5 -6.5,-6.5
Mechanical 13:
  lines w0.1: -6.5,-6.5 6.5,-6.5 6.5,6.5 -6.5,6.5 -6.5,-6.5
Mechanical 15:
  lines w0.1: -0.5,0 0.5,0 ; 0,-0.5 0,0.5 ; -7.5,-7.5 7.5,-7.5 7.5,7.5 -7.5,7.5 -7.5,-7.5
3D body: height 1.2, standoff 0.2, extent -6.5,-6.5 6.5,6.5

## BGA65P21X21-272 [mm] "BGA, 209-Leads, Body 13x13mm, Pitch 0.65mm"
height 1.3
pads (272):
  round 0.35 smd: A1(-6.5,6.5) A2(-5.85,6.5) A3(-5.2,6.5) A4(-4.55,6.5) A5(-3.9,6.5) A6(-3.25,6.5) A7(-2.6,6.5) A8(-1.95,6.5) A9(-1.3,6.5) A10(-0.65,6.5) A11(0,6.5) A12(0.65,6.5) A13(1.3,6.5) A14(1.95,6.5) A15(2.6,6.5) A16(3.25,6.5) A17(3.9,6.5) A18(4.55,6.5) A19(5.2,6.5) A20(5.85,6.5) A21(6.5,6.5) AA1(-6.5,-6.5) AA2(-5.85,-6.5) AA3(-5.2,-6.5) AA4(-4.55,-6.5) AA5(-3.9,-6.5) AA6(-3.25,-6.5) AA7(-2.6,-6.5) AA8(-1.95,-6.5) AA9(-1.3,-6.5) AA10(-0.65,-6.5) AA11(0,-6.5) AA12(0.65,-6.5) AA13(1.3,-6.5) AA14(1.95,-6.5) AA15(2.6,-6.5) AA16(3.25,-6.5) AA17(3.9,-6.5) AA18(4.55,-6.5) AA19(5.2,-6.5) AA20(5.85,-6.5) AA21(6.5,-6.5) B1(-6.5,5.85) B2(-5.85,5.85) B3(-5.2,5.85) B4(-4.55,5.85) B5(-3.9,5.85) B6(-3.25,5.85) B7(-2.6,5.85) B8(-1.95,5.85) B9(-1.3,5.85) B10(-0.65,5.85) B11(0,5.85) B12(0.65,5.85) B13(1.3,5.85) B14(1.95,5.85) B15(2.6,5.85) B16(3.25,5.85) B17(3.9,5.85) B18(4.55,5.85) B19(5.2,5.85) B20(5.85,5.85) B21(6.5,5.85) C1(-6.5,5.2) C2(-5.85,5.2) C3(-5.2,5.2) C4(-4.55,5.2) C5(-3.9,5.2) C6(-3.25,5.2) C7(-2.6,5.2) C8(-1.95,5.2) C9(-1.3,5.2) C10(-0.65,5.2) C11(0,5.2) C12(0.65,5.2) C13(1.3,5.2) C14(1.95,5.2) C15(2.6,5.2) C16(3.25,5.2) C17(3.9,5.2) C18(4.55,5.2) C19(5.2,5.2) C20(5.85,5.2) C21(6.5,5.2) D1(-6.5,4.55) D2(-5.85,4.55) D3(-5.2,4.55) D4(-4.55,4.55) D5(-3.9,4.55) D6(-3.25,4.55) D7(-2.6,4.55) D8(-1.95,4.55) D9(-1.3,4.55) D10(-0.65,4.55) D11(0,4.55) D12(0.65,4.55) D13(1.3,4.55) D14(1.95,4.55) D15(2.6,4.55) D16(3.25,4.55) D17(3.9,4.55) D18(4.55,4.55) D19(5.2,4.55) D20(5.85,4.55) D21(6.5,4.55) E1(-6.5,3.9) E2(-5.85,3.9) E3(-5.2,3.9) E4(-4.55,3.9) E18(4.55,3.9) E19(5.2,3.9) E20(5.85,3.9) E21(6.5,3.9) F1(-6.5,3.25) F2(-5.85,3.25) F3(-5.2,3.25) F4(-4.55,3.25) F18(4.55,3.25) F19(5.2,3.25) F20(5.85,3.25) F21(6.5,3.25) G1(-6.5,2.6) G2(-5.85,2.6) G3(-5.2,2.6) G4(-4.55,2.6) G18(4.55,2.6) G19(5.2,2.6) G20(5.85,2.6) G21(6.5,2.6) H1(-6.5,1.95) H2(-5.85,1.95) H3(-5.2,1.95) H4(-4.55,1.95) H18(4.55,1.95) H19(5.2,1.95) H20(5.85,1.95) H21(6.5,1.95) J1(-6.5,1.3) J2(-5.85,1.3) J3(-5.2,1.3) J4(-4.55,1.3) J18(4.55,1.3) J19(5.2,1.3) J20(5.85,1.3) J21(6.5,1.3) K1(-6.5,0.65) K2(-5.85,0.65) K3(-5.2,0.65) K4(-4.55,0.65) K18(4.55,0.65) K19(5.2,0.65) K20(5.85,0.65) K21(6.5,0.65) L1(-6.5,0) L2(-5.85,0) L3(-5.2,0) L4(-4.55,0) L18(4.55,0) L19(5.2,0) L20(5.85,0) L21(6.5,0) M1(-6.5,-0.65) M2(-5.85,-0.65) M3(-5.2,-0.65) M4(-4.55,-0.65) M18(4.55,-0.65) M19(5.2,-0.65) M20(5.85,-0.65) M21(6.5,-0.65) N1(-6.5,-1.3) N2(-5.85,-1.3) N3(-5.2,-1.3) N4(-4.55,-1.3) N18(4.55,-1.3) N19(5.2,-1.3) N20(5.85,-1.3) N21(6.5,-1.3) P1(-6.5,-1.95) P2(-5.85,-1.95) P3(-5.2,-1.95) P4(-4.55,-1.95) P18(4.55,-1.95) P19(5.2,-1.95) P20(5.85,-1.95) P21(6.5,-1.95) R1(-6.5,-2.6) R2(-5.85,-2.6) R3(-5.2,-2.6) R4(-4.55,-2.6) R18(4.55,-2.6) R19(5.2,-2.6) R20(5.85,-2.6) R21(6.5,-2.6) T1(-6.5,-3.25) T2(-5.85,-3.25) T3(-5.2,-3.25) T4(-4.55,-3.25) T18(4.55,-3.25) T19(5.2,-3.25) T20(5.85,-3.25) T21(6.5,-3.25) U1(-6.5,-3.9) U2(-5.85,-3.9) U3(-5.2,-3.9) U4(-4.55,-3.9) U18(4.55,-3.9) U19(5.2,-3.9) U20(5.85,-3.9) U21(6.5,-3.9) V1(-6.5,-4.55) V2(-5.85,-4.55) V3(-5.2,-4.55) V4(-4.55,-4.55) V5(-3.9,-4.55) V6(-3.25,-4.55) V7(-2.6,-4.55) V8(-1.95,-4.55) V9(-1.3,-4.55) V10(-0.65,-4.55) V11(0,-4.55) V12(0.65,-4.55) V13(1.3,-4.55) V14(1.95,-4.55) V15(2.6,-4.55) V16(3.25,-4.55) V17(3.9,-4.55) V18(4.55,-4.55) V19(5.2,-4.55) V20(5.85,-4.55) V21(6.5,-4.55) W1(-6.5,-5.2) W2(-5.85,-5.2) W3(-5.2,-5.2) W4(-4.55,-5.2) W5(-3.9,-5.2) W6(-3.25,-5.2) W7(-2.6,-5.2) W8(-1.95,-5.2) W9(-1.3,-5.2) W10(-0.65,-5.2) W11(0,-5.2) W12(0.65,-5.2) W13(1.3,-5.2) W14(1.95,-5.2) W15(2.6,-5.2) W16(3.25,-5.2) W17(3.9,-5.2) W18(4.55,-5.2) W19(5.2,-5.2) W20(5.85,-5.2) W21(6.5,-5.2) Y1(-6.5,-5.85) Y2(-5.85,-5.85) Y3(-5.2,-5.85) Y4(-4.55,-5.85) Y5(-3.9,-5.85) Y6(-3.25,-5.85) Y7(-2.6,-5.85) Y8(-1.95,-5.85) Y9(-1.3,-5.85) Y10(-0.65,-5.85) Y11(0,-5.85) Y12(0.65,-5.85) Y13(1.3,-5.85) Y14(1.95,-5.85) Y15(2.6,-5.85) Y16(3.25,-5.85) Y17(3.9,-5.85) Y18(4.55,-5.85) Y19(5.2,-5.85) Y20(5.85,-5.85) Y21(6.5,-5.85)
Top Overlay:
  circle w0.25: c-8.15,6.5 r0.125
  region: -6.5,7.5 -7.5,6.5 -7.5,7.5
  lines w0.2: -7.5,6.5 -6.5,7.5 ; -7.5,-7.5 7.5,-7.5 7.5,7.5 -7.5,7.5 -7.5,-7.5
Mechanical 13:
  lines w0.1: -7.5,-7.5 7.5,-7.5 7.5,7.5 -7.5,7.5 -7.5,-7.5
Mechanical 15:
  lines w0.1: -0.5,0 0.5,0 ; 0,-0.5 0,0.5 ; -8.5,-8.5 8.5,-8.5 8.5,8.5 -8.5,8.5 -8.5,-8.5
3D body: height 1.3, standoff 0.4, extent -7.5,-7.5 7.5,7.5

## BGA80P6X6-36 [mm] "36-Ball Low Profile Ball Grid Array 0.8 mm Pitch"
height 1.7
pads (36):
  round 0.45 smd: A1(-2,2) A2(-1.2,2) A3(-0.4,2) A4(0.4,2) A5(1.2,2) A6(2,2) B1(-2,1.2) B2(-1.2,1.2) B3(-0.4,1.2) B4(0.4,1.2) B5(1.2,1.2) B6(2,1.2) C1(-2,0.4) C2(-1.2,0.4) C3(-0.4,0.4) C4(0.4,0.4) C5(1.2,0.4) C6(2,0.4) D1(-2,-0.4) D2(-1.2,-0.4) D3(-0.4,-0.4) D4(0.4,-0.4) D5(1.2,-0.4) D6(2,-0.4) E1(-2,-1.2) E2(-1.2,-1.2) E3(-0.4,-1.2) E4(0.4,-1.2) E5(1.2,-1.2) E6(2,-1.2) F1(-2,-2) F2(-1.2,-2) F3(-0.4,-2) F4(0.4,-2) F5(1.2,-2) F6(2,-2)
Top Overlay:
  circle w0.25: c-3.625,2 r0.125
  region: -1.975,2.975 -2.975,1.975 -2.975,2.975
  lines w0.2: -2.975,1.975 -1.975,2.975 ; -2.975,-2.975 -2.975,2.975 2.975,2.975 2.975,-2.975 -2.975,-2.975
Mechanical 13:
  lines w0.1: -2.975,-2.975 -2.975,2.975 2.975,2.975 2.975,-2.975 -2.975,-2.975
Mechanical 15:
  lines w0.1: -0.5,0 0.5,0 ; 0,-0.5 0,0.5 ; -3.975,-3.975 -3.975,3.975 3.975,3.975 3.975,-3.975 -3.975,-3.975
3D body: height 1.7, standoff 0, extent -2.975,-2.975 2.975,2.975

## BGA80P6X8-48A [mm] "48-Ball Fine Pitch Ball Grid Array Rectangular 0.8 mm Pitch"
height 1.2
pads (48):
  round 0.25 smd: A1(-2,2.8) A2(-1.2,2.8) A3(-0.4,2.8) A4(0.4,2.8) A5(1.2,2.8) A6(2,2.8) B1(-2,2) B2(-1.2,2) B3(-0.4,2) B4(0.4,2) B5(1.2,2) B6(2,2) C1(-2,1.2) C2(-1.2,1.2) C3(-0.4,1.2) C4(0.4,1.2) C5(1.2,1.2) C6(2,1.2) D1(-2,0.4) D2(-1.2,0.4) D3(-0.4,0.4) D4(0.4,0.4) D5(1.2,0.4) D6(2,0.4) E1(-2,-0.4) E2(-1.2,-0.4) E3(-0.4,-0.4) E4(0.4,-0.4) E5(1.2,-0.4) E6(2,-0.4) F1(-2,-1.2) F2(-1.2,-1.2) F3(-0.4,-1.2) F4(0.4,-1.2) F5(1.2,-1.2) F6(2,-1.2) G1(-2,-2) G2(-1.2,-2) G3(-0.4,-2) G4(0.4,-2) G5(1.2,-2) G6(2,-2) H1(-2,-2.8) H2(-1.2,-2.8) H3(-0.4,-2.8) H4(0.4,-2.8) H5(1.2,-2.8) H6(2,-2.8)
Top Overlay:
  circle w0.25: c-3.725,2.8 r0.125
  region: -2.075,4.075 -3.075,3.075 -3.075,4.075
  lines w0.2: -3.075,3.075 -2.075,4.075 ; -3.075,-4.075 -3.075,4.075 3.075,4.075 3.075,-4.075 -3.075,-4.075
Mechanical 13:
  lines w0.1: -3.075,-4.075 -3.075,4.075 3.075,4.075 3.075,-4.075 -3.075,-4.075
Mechanical 15:
  lines w0.1: -0.5,0 0.5,0 ; 0,-0.5 0,0.5 ; -4.075,-5.075 -4.075,5.075 4.075,5.075 4.075,-5.075 -4.075,-5.075
3D body: height 1.2, standoff 0, extent -3.075,-4.075 3.075,4.075

## BGA80P6X8-48B [mm] "BGA, 48-Leads, Body 9x8mm, Pitch 0.8mm"
height 1.2
pads (48):
  round 0.35 smd: A1(-2,2.8) A2(-1.2,2.8) A3(-0.4,2.8) A4(0.4,2.8) A5(1.2,2.8) A6(2,2.8) B1(-2,2) B2(-1.2,2) B3(-0.4,2) B4(0.4,2) B5(1.2,2) B6(2,2) C1(-2,1.2) C2(-1.2,1.2) C3(-0.4,1.2) C4(0.4,1.2) C5(1.2,1.2) C6(2,1.2) D1(-2,0.4) D2(-1.2,0.4) D3(-0.4,0.4) D4(0.4,0.4) D5(1.2,0.4) D6(2,0.4) E1(-2,-0.4) E2(-1.2,-0.4) E3(-0.4,-0.4) E4(0.4,-0.4) E5(1.2,-0.4) E6(2,-0.4) F1(-2,-1.2) F2(-1.2,-1.2) F3(-0.4,-1.2) F4(0.4,-1.2) F5(1.2,-1.2) F6(2,-1.2) G1(-2,-2) G2(-1.2,-2) G3(-0.4,-2) G4(0.4,-2) G5(1.2,-2) G6(2,-2) H1(-2,-2.8) H2(-1.2,-2.8) H3(-0.4,-2.8) H4(0.4,-2.8) H5(1.2,-2.8) H6(2,-2.8)
Top Overlay:
  circle w0.25: c-4.65,2.8 r0.125
  region: -3,4.5 -4,3.5 -4,4.5
  lines w0.2: -4,3.5 -3,4.5 ; -4,-4.5 -4,4.5 4,4.5 4,-4.5 -4,-4.5
Mechanical 13:
  lines w0.1: -4,-4.5 -4,4.5 4,4.5 4,-4.5 -4,-4.5
Mechanical 15:
  lines w0.1: -0.5,0 0.5,0 ; 0,-0.5 0,0.5 ; -5,-5.5 -5,5.5 5,5.5 5,-5.5 -5,-5.5
3D body: height 1.2, standoff 0, extent -4,-4.5 4,4.5

## BGA80P7X7-48 [mm] "48-Ball Chip Scale Ball Grid Array (CS48)"
height 1.8
pads (48):
  round 0.45 smd: A1(-2.4,2.4) A2(-1.6,2.4) A3(-0.8,2.4) A4(0,2.4) A5(0.8,2.4) A6(1.6,2.4) A7(2.4,2.4) B1(-2.4,1.6) B2(-1.6,1.6) B3(-0.8,1.6) B4(0,1.6) B5(0.8,1.6) B6(1.6,1.6) B7(2.4,1.6) C1(-2.4,0.8) C2(-1.6,0.8) C3(-0.8,0.8) C4(0,0.8) C5(0.8,0.8) C6(1.6,0.8) C7(2.4,0.8) D1(-2.4,0) D2(-1.6,0) D3(-0.8,0) D4(0,0) D6(1.6,0) D7(2.4,0) E1(-2.4,-0.8) E2(-1.6,-0.8) E3(-0.8,-0.8) E4(0,-0.8) E5(0.8,-0.8) E6(1.6,-0.8) E7(2.4,-0.8) F1(-2.4,-1.6) F2(-1.6,-1.6) F3(-0.8,-1.6) F4(0,-1.6) F5(0.8,-1.6) F6(1.6,-1.6) F7(2.4,-1.6) G1(-2.4,-2.4) G2(-1.6,-2.4) G3(-0.8,-2.4) G4(0,-2.4) G5(0.8,-2.4) G6(1.6,-2.4) G7(2.4,-2.4)
Top Overlay:
  circle w0.25: c-4.15,2.4 r0.125
  region: -2.5,3.5 -3.5,2.5 -3.5,3.5
  lines w0.2: -3.5,2.5 -2.5,3.5 ; -3.5,-3.5 3.5,-3.5 3.5,3.5 -3.5,3.5 -3.5,-3.5
Mechanical 13:
  lines w0.1: -3.5,-3.5 3.5,-3.5 3.5,3.5 -3.5,3.5 -3.5,-3.5
Mechanical 15:
  lines w0.1: -0.5,0 0.5,0 ; 0,-0.5 0,0.5 ; -4.5,-4.5 4.5,-4.5 4.5,4.5 -4.5,4.5 -4.5,-4.5
3D body: height 1.8, standoff 0, extent -3.5,-3.5 3.5,3.5

## BGA80P7X7-49 [mm] "BGA, 49-Leads, Body 7x7mm, Pitch 0.8mm"
height 1.5
pads (49):
  round 0.4 smd: A1(-2.4,2.4) A2(-1.6,2.4) A3(-0.8,2.4) A4(0,2.4) A5(0.8,2.4) A6(1.6,2.4) A7(2.4,2.4) B1(-2.4,1.6) B2(-1.6,1.6) B3(-0.8,1.6) B4(0,1.6) B5(0.8,1.6) B6(1.6,1.6) B7(2.4,1.6) C1(-2.4,0.8) C2(-1.6,0.8) C3(-0.8,0.8) C4(0,0.8) C5(0.8,0.8) C6(1.6,0.8) C7(2.4,0.8) D1(-2.4,0) D2(-1.6,0) D3(-0.8,0) D4(0,0) D5(0.8,0) D6(1.6,0) D7(2.4,0) E1(-2.4,-0.8) E2(-1.6,-0.8) E3(-0.8,-0.8) E4(0,-0.8) E5(0.8,-0.8) E6(1.6,-0.8) E7(2.4,-0.8) F1(-2.4,-1.6) F2(-1.6,-1.6) F3(-0.8,-1.6) F4(0,-1.6) F5(0.8,-1.6) F6(1.6,-1.6) F7(2.4,-1.6) G1(-2.4,-2.4) G2(-1.6,-2.4) G3(-0.8,-2.4) G4(0,-2.4) G5(0.8,-2.4) G6(1.6,-2.4) G7(2.4,-2.4)
Top Overlay:
  circle w0.25: c-4.15,2.4 r0.125
  region: -2.5,3.5 -3.5,2.5 -3.5,3.5
  lines w0.2: -3.5,2.5 -2.5,3.5 ; -3.5,-3.5 3.5,-3.5 3.5,3.5 -3.5,3.5 -3.5,-3.5
Mechanical 13:
  lines w0.1: -3.5,-3.5 3.5,-3.5 3.5,3.5 -3.5,3.5 -3.5,-3.5
Mechanical 15:
  lines w0.1: -0.5,0 0.5,0 ; 0,-0.5 0,0.5 ; -4.5,-4.5 4.5,-4.5 4.5,4.5 -4.5,4.5 -4.5,-4.5
3D body: height 1.5, standoff 0, extent -3.5,-3.5 3.5,3.5

## BGA80P7X7-49A [mm] "BGA, 49-Leads, Body 7x7mm, Pitch 0.8mm"
height 1.5
pads (49):
  round 0.45 smd: A1(-2.4,2.4) A2(-1.6,2.4) A3(-0.8,2.4) A4(0,2.4) A5(0.8,2.4) A6(1.6,2.4) A7(2.4,2.4) B1(-2.4,1.6) B2(-1.6,1.6) B3(-0.8,1.6) B4(0,1.6) B5(0.8,1.6) B6(1.6,1.6) B7(2.4,1.6) C1(-2.4,0.8) C2(-1.6,0.8) C3(-0.8,0.8) C4(0,0.8) C5(0.8,0.8) C6(1.6,0.8) C7(2.4,0.8) D1(-2.4,0) D2(-1.6,0) D3(-0.8,0) D4(0,0) D5(0.8,0) D6(1.6,0) D7(2.4,0) E1(-2.4,-0.8) E2(-1.6,-0.8) E3(-0.8,-0.8) E4(0,-0.8) E5(0.8,-0.8) E6(1.6,-0.8) E7(2.4,-0.8) F1(-2.4,-1.6) F2(-1.6,-1.6) F3(-0.8,-1.6) F4(0,-1.6) F5(0.8,-1.6) F6(1.6,-1.6) F7(2.4,-1.6) G1(-2.4,-2.4) G2(-1.6,-2.4) G3(-0.8,-2.4) G4(0,-2.4) G5(0.8,-2.4) G6(1.6,-2.4) G7(2.4,-2.4)
Top Overlay:
  circle w0.25: c-4.15,2.4 r0.125
  region: -2.5,3.5 -3.5,2.5 -3.5,3.5
  lines w0.2: -3.5,2.5 -2.5,3.5 ; -3.5,-3.5 3.5,-3.5 3.5,3.5 -3.5,3.5 -3.5,-3.5
Mechanical 13:
  lines w0.1: -3.5,-3.5 3.5,-3.5 3.5,3.5 -3.5,3.5 -3.5,-3.5
Mechanical 15:
  lines w0.1: -0.5,0 0.5,0 ; 0,-0.5 0,0.5 ; -4.5,-4.5 4.5,-4.5 4.5,4.5 -4.5,4.5 -4.5,-4.5
3D body: height 1.5, standoff 0, extent -3.5,-3.5 3.5,3.5

## BGA80P8X6-48 [mm] "BGA, 48-Leads, Body 7x7mm, Pitch 0.8mm"
height 1.2
pads (48):
  round 0.25 smd: A1(-2.8,2) A2(-2,2) A3(-1.2,2) A4(-0.4,2) A5(0.4,2) A6(1.2,2) A7(2,2) A8(2.8,2) B1(-2.8,1.2) B2(-2,1.2) B3(-1.2,1.2) B4(-0.4,1.2) B5(0.4,1.2) B6(1.2,1.2) B7(2,1.2) B8(2.8,1.2) C1(-2.8,0.4) C2(-2,0.4) C3(-1.2,0.4) C4(-0.4,0.4) C5(0.4,0.4) C6(1.2,0.4) C7(2,0.4) C8(2.8,0.4) D1(-2.8,-0.4) D2(-2,-0.4) D3(-1.2,-0.4) D4(-0.4,-0.4) D5(0.4,-0.4) D6(1.2,-0.4) D7(2,-0.4) D8(2.8,-0.4) E1(-2.8,-1.2) E2(-2,-1.2) E3(-1.2,-1.2) E4(-0.4,-1.2) E5(0.4,-1.2) E6(1.2,-1.2) E7(2,-1.2) E8(2.8,-1.2) F1(-2.8,-2) F2(-2,-2) F3(-1.2,-2) F4(-0.4,-2) F5(0.4,-2) F6(1.2,-2) F7(2,-2) F8(2.8,-2)
Top Overlay:
  circle w0.25: c-4.15,2.8 r0.125
  region: -2.5,3.5 -3.5,2.5 -3.5,3.5
  lines w0.2: -3.5,2.5 -2.5,3.5 ; -3.5,-3.5 -3.5,3.5 3.5,3.5 3.5,-3.5 -3.5,-3.5
Mechanical 13:
  lines w0.1: -3.5,-3.5 -3.5,3.5 3.5,3.5 3.5,-3.5 -3.5,-3.5
Mechanical 15:
  lines w0.1: -0.5,0 0.5,0 ; 0,-0.5 0,0.5 ; -4.5,-4.5 -4.5,4.5 4.5,4.5 4.5,-4.5 -4.5,-4.5
3D body: height 1.2, standoff 0, extent -3.5,-3.5 3.5,3.5

## BGA80P8X8-64 [mm] "BGA, 64-Leads, Body 8x8mm, Pitch 0.8mm"
height 1.5
pads (64):
  round 0.4 smd: A1(-2.8,2.8) A2(-2,2.8) A3(-1.2,2.8) A4(-0.4,2.8) A5(0.4,2.8) A6(1.2,2.8) A7(2,2.8) A8(2.8,2.8) B1(-2.8,2) B2(-2,2) B3(-1.2,2) B4(-0.4,2) B5(0.4,2) B6(1.2,2) B7(2,2) B8(2.8,2) C1(-2.8,1.2) C2(-2,1.2) C3(-1.2,1.2) C4(-0.4,1.2) C5(0.4,1.2) C6(1.2,1.2) C7(2,1.2) C8(2.8,1.2) D1(-2.8,0.4) D2(-2,0.4) D3(-1.2,0.4) D4(-0.4,0.4) D5(0.4,0.4) D6(1.2,0.4) D7(2,0.4) D8(2.8,0.4) E1(-2.8,-0.4) E2(-2,-0.4) E3(-1.2,-0.4) E4(-0.4,-0.4) E5(0.4,-0.4) E6(1.2,-0.4) E7(2,-0.4) E8(2.8,-0.4) F1(-2.8,-1.2) F2(-2,-1.2) F3(-1.2,-1.2) F4(-0.4,-1.2) F5(0.4,-1.2) F6(1.2,-1.2) F7(2,-1.2) F8(2.8,-1.2) G1(-2.8,-2) G2(-2,-2) G3(-1.2,-2) G4(-0.4,-2) G5(0.4,-2) G6(1.2,-2) G7(2,-2) G8(2.8,-2) H1(-2.8,-2.8) H2(-2,-2.8) H3(-1.2,-2.8) H4(-0.4,-2.8) H5(0.4,-2.8) H6(1.2,-2.8) H7(2,-2.8) H8(2.8,-2.8)
Top Overlay:
  circle w0.25: c-4.65,2.8 r0.125
  region: -3,4 -4,3 -4,4
  lines w0.2: -4,3 -3,4 ; -4,-4 4,-4 4,4 -4,4 -4,-4
Mechanical 13:
  lines w0.1: -4,-4 4,-4 4,4 -4,4 -4,-4
Mechanical 15:
  lines w0.1: -0.5,0 0.5,0 ; 0,-0.5 0,0.5 ; -5,-5 5,-5 5,5 -5,5 -5,-5
3D body: height 1.1, standoff 0, extent -4,-4 4,4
